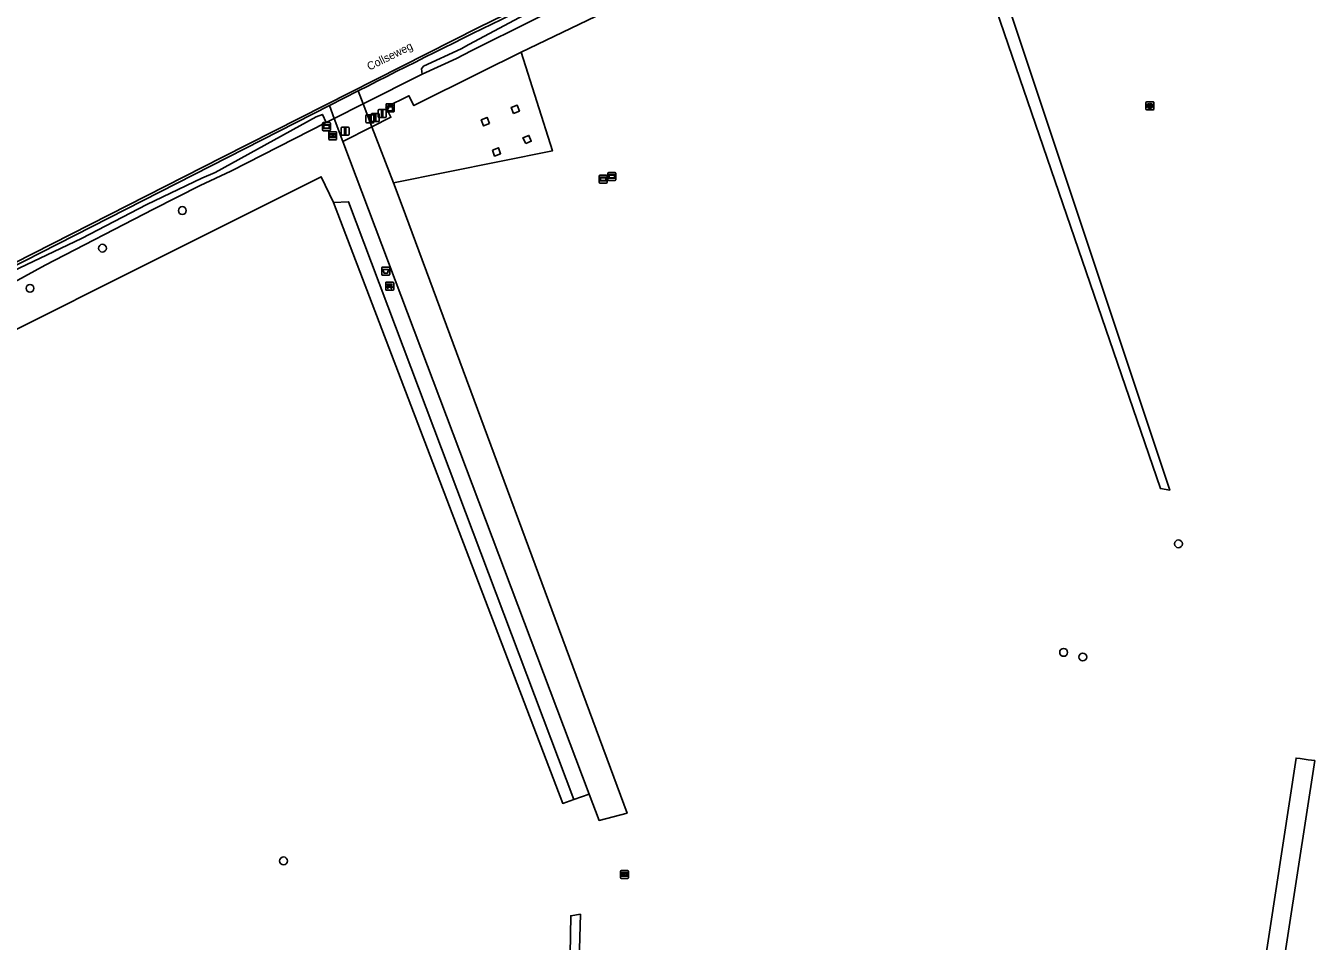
# Model space of a CAD drawing. Extents: x 164494 to 166241, y 382475 to 384494.
# Drawn here: x 164952.3 to 165113.4, y 383627.3 to 383741.6 of the extents above; entities that cross this region are included whole.
import ezdxf

# ---------------------------------------------------------------- set-up
doc = ezdxf.new("R2010")
doc.units = 0
for name, color, linetype in [('IMGEO_Afsluitpaal', 7, 'Continuous'), ('IMGEO_Afvalbak', 7, 'Continuous'), ('IMGEO_Bank', 7, 'Continuous'), ('IMGEO_Berm_halfverhard', 7, 'Continuous'), ('IMGEO_Boom', 7, 'Continuous'), ('IMGEO_Bouwland', 7, 'Continuous'), ('IMGEO_Groenvoorziening', 7, 'Continuous'), ('IMGEO_Hek', 7, 'Continuous'), ('IMGEO_Hoogspanningsmast', 7, 'Continuous'), ('IMGEO_Informatiebord', 7, 'Continuous'), ('IMGEO_Kast', 7, 'Continuous'), ('IMGEO_Loofbos', 7, 'Continuous'), ('IMGEO_Openbare_ruimte_label', 7, 'Continuous'), ('IMGEO_Rijbaan_lokaal_gesloten', 7, 'Continuous'), ('IMGEO_Rioolput', 7, 'Continuous'), ('IMGEO_Verklikker', 7, 'Continuous'), ('IMGEO_Voetpad_halfverhard', 7, 'Continuous'), ('IMGEO_Waterloop', 7, 'Continuous'), ('IMGEO_Wegwijzer', 7, 'Continuous')]:
    doc.layers.add(name, color=color, linetype=linetype)

msp = doc.modelspace()

# ---------------------------------------------------------------- linework, layer by layer
at = {"layer": 'IMGEO_Afsluitpaal'}
for p, q in [((164995.53, 383730.61), (164996.32, 383730.61)), ((164996.32, 383730.61), (164995.53, 383730.61)), ((164996.31, 383730.23), (164996.31, 383731.03)), ((164996.31, 383731.03), (164996.31, 383730.23)), ((164996.41, 383731.13), (164997.19, 383731.13)), ((164997.19, 383731.13), (164996.41, 383731.13)), ((164997.29, 383731.03), (164997.29, 383730.23)), ((164997.29, 383730.23), (164997.29, 383731.03)), ((164994.78, 383729.55), (164994.78, 383730.35)), ((164994.78, 383730.35), (164994.78, 383729.55)), ((164994.88, 383730.45), (164995.67, 383730.45)), ((164995.67, 383730.45), (164994.88, 383730.45)), ((164995.67, 383729.45), (164994.88, 383729.45)), ((164994.88, 383729.45), (164995.67, 383729.45)), ((164995.43, 383729.71), (164995.43, 383730.51)), ((164995.43, 383730.51), (164995.43, 383729.71)), ((164996.32, 383729.61), (164995.53, 383729.61)), ((164995.53, 383729.61), (164996.32, 383729.61)), ((164995.77, 383730.35), (164995.77, 383729.55)), ((164995.77, 383729.55), (164995.77, 383730.35)), ((164997.19, 383730.13), (164996.41, 383730.13)), ((164996.41, 383730.13), (164997.19, 383730.13)), ((164996.42, 383730.51), (164996.42, 383729.71)), ((164996.42, 383729.71), (164996.42, 383730.51)), ((164991.68, 383728.02), (164991.68, 383728.82)), ((164991.68, 383728.82), (164991.68, 383728.02)), ((164991.78, 383728.92), (164992.57, 383728.92)), ((164992.57, 383728.92), (164991.78, 383728.92)), ((164992.57, 383727.92), (164991.78, 383727.92)), ((164991.78, 383727.92), (164992.57, 383727.92)), ((164992.67, 383728.82), (164992.67, 383728.02)), ((164992.67, 383728.02), (164992.67, 383728.82))]:
    msp.add_line(p, q, dxfattribs=at)
for points in [[(164996.72, 383731.01), (164996.88, 383731.01), (164996.88, 383730.26), (164996.72, 383730.26), (164996.72, 383731.01)], [(164995.2, 383730.32), (164995.35, 383730.32), (164995.35, 383729.57), (164995.2, 383729.57), (164995.2, 383730.32)], [(164995.85, 383730.48), (164996, 383730.48), (164996, 383729.73), (164995.85, 383729.73), (164995.85, 383730.48)], [(164992.1, 383728.8), (164992.25, 383728.8), (164992.25, 383728.05), (164992.1, 383728.05), (164992.1, 383728.8)]]:
    msp.add_lwpolyline(points, dxfattribs=at)
for centre, start, end in [((164995.53, 383730.51), 90, 180), ((164995.53, 383730.51), 90, 180), ((164996.41, 383731.03), 90, 180), ((164996.41, 383731.03), 90, 180), ((164996.32, 383730.51), 0, 90), ((164996.32, 383730.51), 360, 90), ((164997.19, 383731.03), 0, 90), ((164997.19, 383731.03), 360, 90), ((164994.88, 383730.35), 90, 180), ((164994.88, 383730.35), 90, 180), ((164994.88, 383729.55), 180, 270), ((164994.88, 383729.55), 180, 270), ((164995.53, 383729.71), 180, 270), ((164995.53, 383729.71), 180, 270), ((164995.67, 383730.35), 0, 90), ((164995.67, 383730.35), 360, 90), ((164995.67, 383729.55), 270, 0), ((164995.67, 383729.55), 270, 0), ((164996.41, 383730.23), 180, 270), ((164996.41, 383730.23), 180, 270), ((164996.32, 383729.71), 270, 0), ((164996.32, 383729.71), 270, 0), ((164997.19, 383730.23), 270, 0), ((164997.19, 383730.23), 270, 0), ((164991.78, 383728.82), 90, 180), ((164991.78, 383728.82), 90, 180), ((164991.78, 383728.02), 180, 270), ((164991.78, 383728.02), 180, 270), ((164992.57, 383728.82), 0, 90), ((164992.57, 383728.82), 360, 90), ((164992.57, 383728.02), 270, 0), ((164992.57, 383728.02), 270, 0)]:
    msp.add_arc(centre, 0.1, start, end, dxfattribs=at)
at = {"layer": 'IMGEO_Afvalbak'}
for p, q in [((164996.75, 383710.53), (164996.75, 383711.33)), ((164996.75, 383711.33), (164996.75, 383710.53)), ((164996.85, 383711.43), (164997.64, 383711.43)), ((164997.64, 383711.43), (164996.85, 383711.43)), ((164997.74, 383711.33), (164997.74, 383710.53)), ((164997.74, 383710.53), (164997.74, 383711.33)), ((164997.64, 383710.43), (164996.85, 383710.43)), ((164996.85, 383710.43), (164997.64, 383710.43))]:
    msp.add_line(p, q, dxfattribs=at)
msp.add_lwpolyline([(164996.89, 383711.14), (164997.6, 383711.14), (164997.45, 383710.67), (164997.04, 383710.67), (164996.89, 383711.14)], dxfattribs=at)
for centre, start, end in [((164996.85, 383711.33), 90, 180), ((164996.85, 383711.33), 90, 180), ((164997.64, 383711.33), 0, 90), ((164997.64, 383711.33), 360, 90), ((164996.85, 383710.53), 180, 270), ((164996.85, 383710.53), 180, 270), ((164997.64, 383710.53), 270, 0), ((164997.64, 383710.53), 270, 0)]:
    msp.add_arc(centre, 0.1, start, end, dxfattribs=at)
at = {"layer": 'IMGEO_Bank'}
for p, q in [((164997.24, 383708.63), (164997.24, 383709.47)), ((164997.24, 383709.47), (164997.24, 383708.63)), ((164997.31, 383709.55), (164998.15, 383709.55)), ((164998.15, 383709.55), (164997.31, 383709.55)), ((164998.16, 383708.55), (164997.32, 383708.55)), ((164997.32, 383708.55), (164998.16, 383708.55)), ((164997.93, 383708.95), (164997.54, 383708.95)), ((164997.55, 383709.06), (164997.55, 383709.16)), ((164997.59, 383709.16), (164997.59, 383709.06)), ((164997.88, 383709.17), (164997.6, 383709.17)), ((164997.6, 383709.05), (164997.88, 383709.05)), ((164997.88, 383709.06), (164997.88, 383709.16)), ((164997.93, 383709.16), (164997.93, 383709.06)), ((164998.24, 383709.48), (164998.24, 383708.64)), ((164998.24, 383708.64), (164998.24, 383709.48))]:
    msp.add_line(p, q, dxfattribs=at)
for points in [[(164997.48, 383708.95), (164997.34, 383708.95), (164997.45, 383709.05), (164997.54, 383709.05)], [(164997.54, 383709.17), (164997.45, 383709.17), (164997.45, 383709.33), (164998.02, 383709.33), (164998.02, 383709.17), (164997.93, 383709.17)], [(164997.53, 383708.94), (164997.53, 383708.73), (164997.49, 383708.73), (164997.49, 383708.94)], [(164997.93, 383709.05), (164998.02, 383709.05), (164998.13, 383708.95), (164997.99, 383708.95)], [(164997.98, 383708.94), (164997.98, 383708.73), (164997.94, 383708.73), (164997.94, 383708.94)]]:
    msp.add_lwpolyline(points, dxfattribs=at)
for centre, radius, start, end in [((164997.31, 383709.47), 0.0779, 92.4484, 184.2845), ((164997.31, 383709.47), 0.0779, 92.4484, 184.2845), ((164997.31, 383708.63), 0.0779, 182.4484, 274.2845), ((164997.31, 383708.63), 0.0779, 182.4484, 274.2845), ((164997.48, 383708.94), 0.00671, 2.8957, 87.1043), ((164997.54, 383708.94), 0.00671, 92.8957, 177.1043), ((164997.54, 383709.16), 0.00671, 2.8957, 87.1043), ((164997.54, 383709.06), 0.00671, 272.8957, 357.1043), ((164997.6, 383709.16), 0.00671, 92.8957, 177.1043), ((164997.6, 383709.06), 0.00671, 182.8957, 267.1043), ((164997.88, 383709.16), 0.00671, 2.8957, 87.1043), ((164997.88, 383709.06), 0.00671, 272.8957, 357.1043), ((164997.93, 383709.16), 0.00671, 92.8957, 177.1043), ((164997.93, 383709.06), 0.00671, 182.8957, 267.1043), ((164997.93, 383708.94), 0.00671, 2.8957, 87.1043), ((164997.99, 383708.94), 0.00671, 92.8957, 177.1043), ((164998.16, 383709.47), 0.0779, 2.4484, 94.2845), ((164998.16, 383709.47), 0.0779, 2.4484, 94.2845), ((164998.16, 383708.63), 0.0779, 272.4484, 4.2845), ((164998.16, 383708.63), 0.0779, 272.4484, 4.2845)]:
    msp.add_arc(centre, radius, start, end, dxfattribs=at)
at = {"layer": 'IMGEO_Berm_halfverhard'}
msp.add_lwpolyline([(164990.21, 383731.63), (164918.16, 383694.89), (164857.49, 383664.27)], dxfattribs=at)
msp.add_arc((165881.31, 381974.98), 1969.75, 115.53986, 116.78018, dxfattribs=at)
at = {"layer": 'IMGEO_Boom'}
for centre in [(164971.83, 383718.5), (164961.86, 383713.8), (164952.81, 383708.79), (165096.28, 383676.88), (165081.93, 383663.32), (165084.33, 383662.74), (164984.48, 383637.28)]:
    msp.add_circle(centre, 0.489, dxfattribs=at)
at = {"layer": 'IMGEO_Bouwland'}
for points in [[(165145.85, 383799.61), (165106.62, 383781.19), (165067, 383763.68), (165014.17, 383738.3)], [(165014.17, 383738.3), (165018.06, 383725.95), (164998.2, 383721.96)], [(164990.71, 383719.49), (164989.19, 383722.73), (164927.7, 383692)], [(165022.66, 383645.63), (165020.73, 383644.93)]]:
    msp.add_lwpolyline(points, dxfattribs=at)
at = {"layer": 'IMGEO_Groenvoorziening'}
for points in [[(165014.17, 383738.3), (165009.04, 383735.74), (165000.77, 383731.61), (165000.15, 383732.85), (164997.27, 383731.4), (164997.89, 383730.16), (164995.52, 383728.97)], [(165001.78, 383735.55), (164994.43, 383731.82)], [(164989.81, 383729.48), (164990.82, 383729.99)]]:
    msp.add_lwpolyline(points, dxfattribs=at)
at = {"layer": 'IMGEO_Hek'}
msp.add_lwpolyline([(164997.89, 383730.16), (164997.27, 383731.4), (165000.15, 383732.85), (165000.77, 383731.61)], dxfattribs=at)
at = {"layer": 'IMGEO_Hoogspanningsmast'}
for points in [[(165013.2, 383730.62), (165013.95, 383730.93), (165013.65, 383731.67), (165012.93, 383731.38), (165013.2, 383730.62)], [(165010.19, 383729.38), (165009.91, 383730.13), (165009.17, 383729.83), (165009.45, 383729.08), (165010.19, 383729.38)], [(165014.75, 383726.87), (165015.43, 383727.15), (165015.13, 383727.89), (165014.39, 383727.59), (165014.75, 383726.87)], [(165010.57, 383726.05), (165010.85, 383725.3), (165011.6, 383725.6), (165011.32, 383726.35), (165010.57, 383726.05)]]:
    msp.add_lwpolyline(points, dxfattribs=at)
at = {"layer": 'IMGEO_Informatiebord'}
for p, q in [((164990.12, 383727.45), (164990.12, 383728.25)), ((164990.12, 383728.25), (164990.12, 383727.45)), ((164990.22, 383728.35), (164991.01, 383728.35)), ((164991.01, 383728.35), (164990.22, 383728.35)), ((164991.11, 383728.25), (164991.11, 383727.45)), ((164991.11, 383727.45), (164991.11, 383728.25)), ((164991.01, 383727.35), (164990.22, 383727.35)), ((164990.22, 383727.35), (164991.01, 383727.35))]:
    msp.add_line(p, q, dxfattribs=at)
for points in [[(164990.22, 383728.09), (164991.01, 383728.09), (164991.01, 383727.62), (164990.22, 383727.62), (164990.22, 383728.09)], [(164990.28, 383728.02), (164990.28, 383727.69), (164990.56, 383727.69), (164990.56, 383727.9), (164990.66, 383727.9), (164990.67, 383727.69), (164990.94, 383727.69), (164990.94, 383728.02), (164990.67, 383728.02), (164990.67, 383727.94), (164990.56, 383727.94), (164990.56, 383728.02), (164990.28, 383728.02)]]:
    msp.add_lwpolyline(points, dxfattribs=at)
for centre, start, end in [((164990.22, 383728.25), 90, 180), ((164990.22, 383728.25), 90, 180), ((164990.22, 383727.45), 180, 270), ((164990.22, 383727.45), 180, 270), ((164991.01, 383728.25), 0, 90), ((164991.01, 383728.25), 360, 90), ((164991.01, 383727.45), 270, 0), ((164991.01, 383727.45), 270, 0)]:
    msp.add_arc(centre, 0.1, start, end, dxfattribs=at)
at = {"layer": 'IMGEO_Kast'}
for p, q in [((164997.31, 383730.91), (164997.31, 383731.75)), ((164997.31, 383731.75), (164997.31, 383730.91)), ((164997.38, 383731.83), (164998.22, 383731.83)), ((164998.22, 383731.83), (164997.38, 383731.83)), ((164998.23, 383730.84), (164997.39, 383730.84)), ((164997.39, 383730.84), (164998.23, 383730.84)), ((164998.3, 383731.76), (164998.3, 383730.92)), ((164998.3, 383730.92), (164998.3, 383731.76))]:
    msp.add_line(p, q, dxfattribs=at)
for points in [[(164997.5, 383731.63), (164998.1, 383731.63), (164998.1, 383731.54), (164997.5, 383731.54), (164997.5, 383731.63)], [(164997.5, 383731.45), (164998.1, 383731.45), (164998.1, 383730.96), (164997.5, 383730.96), (164997.5, 383731.45)]]:
    msp.add_lwpolyline(points, dxfattribs=at)
msp.add_circle((164997.58, 383731.3), 0.0377, dxfattribs=at)
for centre, start, end in [((164997.38, 383731.76), 92.4484, 184.2845), ((164997.38, 383731.76), 92.4484, 184.2845), ((164997.38, 383730.91), 182.4484, 274.2845), ((164997.38, 383730.91), 182.4484, 274.2845), ((164998.23, 383731.76), 2.4484, 94.2845), ((164998.23, 383731.76), 2.4484, 94.2845), ((164998.23, 383730.91), 272.4484, 4.2845), ((164998.23, 383730.91), 272.4484, 4.2845)]:
    msp.add_arc(centre, 0.0779, start, end, dxfattribs=at)
at = {"layer": 'IMGEO_Loofbos'}
for points in [[(165070.74, 383756.95), (165095.19, 383683.58), (165094.03, 383683.77), (165069.15, 383756.41), (165070.74, 383756.95)], [(164990.71, 383719.49), (164992.61, 383719.6), (165020.73, 383644.93)], [(165020.73, 383644.93), (165019.36, 383644.46), (164990.71, 383719.49)], [(165113.32, 383649.8), (165112.48, 383649.92), (165111.49, 383650.06), (165110.98, 383650.12), (165103.45, 383600.94), (165103.75, 383600.87), (165105.69, 383600.45), (165113.32, 383649.8)], [(165021.58, 383630.63), (165021.18, 383616.11), (165020.13, 383616.03), (165020.36, 383630.43), (165021.58, 383630.63)]]:
    msp.add_lwpolyline(points, dxfattribs=at)
at = {"layer": 'IMGEO_Rijbaan_lokaal_gesloten'}
msp.add_lwpolyline([(164820.83, 383644.04), (164832.44, 383650.98), (164841.27, 383655.96), (164850.2, 383660.84), (164855.28, 383663.57), (164862.3, 383667.12), (164878.88, 383675.63), (164924.55, 383698.62), (164938.76, 383705.81), (164953.21, 383713.15), (164976.85, 383725.17), (165008.84, 383741.37), (165021.76, 383747.71), (165041.41, 383757.04), (165051.25, 383761.78), (165055.83, 383763.95)], dxfattribs=at)
at = {"layer": 'IMGEO_Rioolput'}
for p, q in [((165092.21, 383731.15), (165092.21, 383732.01)), ((165092.28, 383732.08), (165093.14, 383732.08)), ((165093.14, 383731.08), (165092.28, 383731.08)), ((165092.72, 383731.3), (165092.69, 383731.3)), ((165092.7, 383731.86), (165092.72, 383731.86)), ((165093.21, 383732.01), (165093.21, 383731.15))]:
    msp.add_line(p, q, dxfattribs=at)
for points in [[(165092.21, 383731.15), (165092.21, 383732.01)], [(165092.28, 383732.08), (165093.14, 383732.08)], [(165093.14, 383731.08), (165092.28, 383731.08)], [(165092.8, 383731.78), (165092.55, 383731.78), (165092.55, 383731.38)], [(165092.55, 383731.38), (165092.67, 383731.38), (165092.67, 383731.54), (165092.68, 383731.54)], [(165092.72, 383731.7), (165092.67, 383731.7), (165092.67, 383731.62)], [(165092.67, 383731.62), (165092.72, 383731.62)], [(165092.73, 383731.51), (165092.8, 383731.38), (165092.94, 383731.38), (165092.87, 383731.51)], [(165093.21, 383732.01), (165093.21, 383731.15)]]:
    msp.add_lwpolyline(points, dxfattribs=at)
for centre, radius, start, end in [((165092.29, 383732), 0.0765, 91.552, 178.448), ((165092.29, 383732), 0.0765, 91.552, 178.448), ((165092.29, 383731.16), 0.0765, 181.552, 268.448), ((165092.29, 383731.16), 0.0765, 181.552, 268.448), ((165092.68, 383731.49), 0.0533, 26.0293, 88.6989), ((165092.73, 383731.6), 0.0964, 77.0061, 93.1865), ((165092.71, 383731.81), 0.19, 274.7715, 282.9687), ((165092.74, 383731.66), 0.0378, 276.6634, 79.6772), ((165092.8, 383731.67), 0.109, 350.3612, 89.416), ((165092.8, 383731.67), 0.112, 277.5842, 350.9817), ((165092.78, 383731.45), 0.108, 29.5134, 73.7905), ((165093.13, 383732), 0.0765, 1.552, 88.448), ((165093.13, 383732), 0.0765, 1.552, 88.448), ((165093.13, 383731.16), 0.0765, 271.552, 358.448), ((165093.13, 383731.16), 0.0765, 271.552, 358.448)]:
    msp.add_arc(centre, radius, start, end, dxfattribs=at)
for centre, major_axis, ratio, start_param, end_param in [((165092.7, 383731.58), (-0.387, 0.002), 0.722429, 4.712389, 7.853982), ((165092.72, 383731.58), (-0.39, 0.002), 0.717154, 1.570796, 4.712389)]:
    msp.add_ellipse(centre, major_axis=major_axis, ratio=ratio, start_param=start_param, end_param=end_param, dxfattribs=at)
at = {"layer": 'IMGEO_Verklikker'}
for p, q in [((164989.34, 383728.58), (164989.34, 383729.38)), ((164989.34, 383729.38), (164989.34, 383728.58)), ((164989.44, 383729.48), (164990.23, 383729.48)), ((164990.23, 383729.48), (164989.44, 383729.48)), ((164990.33, 383729.38), (164990.33, 383728.58)), ((164990.33, 383728.58), (164990.33, 383729.38)), ((164990.23, 383728.48), (164989.44, 383728.48)), ((164989.44, 383728.48), (164990.23, 383728.48)), ((165023.92, 383722.03), (165023.92, 383722.83)), ((165023.92, 383722.83), (165023.92, 383722.03)), ((165024.02, 383722.93), (165024.81, 383722.93)), ((165024.81, 383722.93), (165024.02, 383722.93)), ((165024.91, 383722.83), (165024.91, 383722.03)), ((165024.91, 383722.03), (165024.91, 383722.83)), ((165024.99, 383722.36), (165024.99, 383723.16)), ((165024.99, 383723.16), (165024.99, 383722.36)), ((165025.09, 383723.26), (165025.88, 383723.26)), ((165025.88, 383723.26), (165025.09, 383723.26)), ((165025.98, 383723.16), (165025.98, 383722.36)), ((165025.98, 383722.36), (165025.98, 383723.16)), ((165024.81, 383721.93), (165024.02, 383721.93)), ((165024.02, 383721.93), (165024.81, 383721.93)), ((165025.88, 383722.26), (165025.09, 383722.26)), ((165025.09, 383722.26), (165025.88, 383722.26))]:
    msp.add_line(p, q, dxfattribs=at)
for points in [[(164989.44, 383729.21), (164990.23, 383729.21), (164990.23, 383728.75), (164989.44, 383728.75), (164989.44, 383729.21)], [(164989.51, 383729.15), (164989.51, 383728.81), (164990.16, 383728.81), (164990.16, 383729.15), (164989.51, 383729.15)], [(165024.02, 383722.67), (165024.81, 383722.67), (165024.81, 383722.2), (165024.02, 383722.2), (165024.02, 383722.67)], [(165024.09, 383722.6), (165024.09, 383722.27), (165024.75, 383722.27), (165024.75, 383722.6), (165024.09, 383722.6)], [(165025.09, 383722.99), (165025.88, 383722.99), (165025.88, 383722.53), (165025.09, 383722.53), (165025.09, 383722.99)], [(165025.16, 383722.93), (165025.16, 383722.59), (165025.82, 383722.59), (165025.82, 383722.93), (165025.16, 383722.93)]]:
    msp.add_lwpolyline(points, dxfattribs=at)
for centre, start, end in [((164989.44, 383729.38), 90, 180), ((164989.44, 383729.38), 90, 180), ((164990.23, 383729.38), 0, 90), ((164990.23, 383729.38), 360, 90), ((164989.44, 383728.58), 180, 270), ((164989.44, 383728.58), 180, 270), ((164990.23, 383728.58), 270, 0), ((164990.23, 383728.58), 270, 0), ((165024.02, 383722.83), 90, 180), ((165024.02, 383722.83), 90, 180), ((165024.81, 383722.83), 0, 90), ((165024.81, 383722.83), 360, 90), ((165025.09, 383723.16), 90, 180), ((165025.09, 383723.16), 90, 180), ((165025.88, 383723.16), 0, 90), ((165025.88, 383723.16), 360, 90), ((165024.02, 383722.03), 180, 270), ((165024.02, 383722.03), 180, 270), ((165024.81, 383722.03), 270, 0), ((165024.81, 383722.03), 270, 0), ((165025.09, 383722.36), 180, 270), ((165025.09, 383722.36), 180, 270), ((165025.88, 383722.36), 270, 0), ((165025.88, 383722.36), 270, 0)]:
    msp.add_arc(centre, 0.1, start, end, dxfattribs=at)
at = {"layer": 'IMGEO_Voetpad_halfverhard'}
for points in [[(164990.21, 383731.63), (164992.01, 383732.54), (164993.81, 383733.45)], [(164994.43, 383731.82), (164993.81, 383733.45)], [(164990.82, 383729.99), (164990.21, 383731.63)], [(164990.82, 383729.99), (164994.43, 383731.82)], [(164995.52, 383728.97), (164994.43, 383731.82)], [(164991.9, 383727.14), (164990.82, 383729.99)], [(164995.52, 383728.97), (164991.9, 383727.14)], [(164998.2, 383721.96), (164995.52, 383728.97)], [(165022.66, 383645.63), (164991.9, 383727.14)], [(164998.2, 383721.96), (164999.29, 383719.09), (165027.4, 383643.26), (165023.9, 383642.33), (165022.66, 383645.63)]]:
    msp.add_lwpolyline(points, dxfattribs=at)
at = {"layer": 'IMGEO_Waterloop'}
for points in [[(165001.78, 383735.55), (165006.07, 383737.5), (165007.93, 383738.43), (165023.34, 383746.14), (165031.57, 383750), (165060.33, 383763.51), (165066.52, 383766.73), (165068.7, 383767.49), (165073.7, 383769.7), (165082.11, 383773.72), (165087.31, 383776), (165090.72, 383777.72), (165094.61, 383779.31), (165106.54, 383785.41), (165136.21, 383799.88)], [(165116.54, 383791.5), (165110.23, 383788.86), (165105.79, 383786.49), (165095.01, 383781.71), (165092.84, 383780.52), (165085.48, 383777.47), (165079.31, 383774.16), (165071.5, 383770.67), (165066.38, 383768.17), (165058.31, 383763.92), (165041.69, 383756.14), (165037.96, 383754.58), (165030.63, 383750.61), (165029.28, 383750), (165025.84, 383748.45), (165016.88, 383743.93), (165015.2, 383743.26), (165007.61, 383739.23), (165006.66, 383738.72), (165001.97, 383736.53), (165001.72, 383736.21), (165001.78, 383735.55)], [(164806.33, 383573.27), (164806.24, 383573.56), (164806.01, 383574.6), (164802.51, 383588.73), (164799.07, 383603.38), (164797.1, 383611.73), (164802.6, 383625.63), (164809.89, 383633.96), (164816.08, 383639.05), (164826.55, 383646.32), (164839.94, 383654.17), (164848.68, 383658.82), (164880.21, 383674.74), (164883.32, 383676.34), (164927.21, 383699.15), (164948.87, 383710.09), (164959.25, 383715), (164967.4, 383719.26), (164974.26, 383722.56), (164975.93, 383723.27), (164988.54, 383730.22), (164989.34, 383730.51), (164989.81, 383729.48)], [(164811.53, 383631.8), (164817.85, 383637.08), (164828.27, 383644.18), (164840.2, 383651.69), (164849.26, 383657.07), (164880.93, 383673.27), (164884.02, 383674.85), (164928.81, 383698.02), (164940.08, 383703.71), (164954.72, 383711.67), (164968.25, 383718.66), (164974.05, 383721.63), (164977.89, 383723.43), (164989.81, 383729.48)]]:
    msp.add_lwpolyline(points, dxfattribs=at)
at = {"layer": 'IMGEO_Wegwijzer'}
for p, q in [((165026.58, 383635.19), (165026.58, 383635.99)), ((165026.58, 383635.99), (165026.58, 383635.19)), ((165026.68, 383636.09), (165027.46, 383636.09)), ((165027.46, 383636.09), (165026.68, 383636.09)), ((165027.56, 383635.99), (165027.56, 383635.19)), ((165027.56, 383635.19), (165027.56, 383635.99)), ((165027.46, 383635.09), (165026.68, 383635.09)), ((165026.68, 383635.09), (165027.46, 383635.09))]:
    msp.add_line(p, q, dxfattribs=at)
for points in [[(165026.68, 383635.82), (165027.46, 383635.82), (165027.46, 383635.36), (165026.68, 383635.36), (165026.68, 383635.82)], [(165026.74, 383635.67), (165026.74, 383635.59), (165026.74, 383635.51), (165027.15, 383635.51), (165027.15, 383635.42), (165027.4, 383635.59), (165027.15, 383635.76), (165027.15, 383635.67), (165026.74, 383635.67)]]:
    msp.add_lwpolyline(points, dxfattribs=at)
for centre, start, end in [((165026.68, 383635.99), 90, 180), ((165026.68, 383635.99), 90, 180), ((165027.46, 383635.99), 0, 90), ((165027.46, 383635.99), 360, 90), ((165026.68, 383635.19), 180, 270), ((165026.68, 383635.19), 180, 270), ((165027.46, 383635.19), 270, 0), ((165027.46, 383635.19), 270, 0)]:
    msp.add_arc(centre, 0.1, start, end, dxfattribs=at)

# ---------------------------------------------------------------- texts
at = {"layer": 'IMGEO_Openbare_ruimte_label'}
msp.add_text('Collseweg', height=1, rotation=26.4882, dxfattribs=at).set_placement((164995.21, 383735.97))

doc.saveas('drawing.dxf')
